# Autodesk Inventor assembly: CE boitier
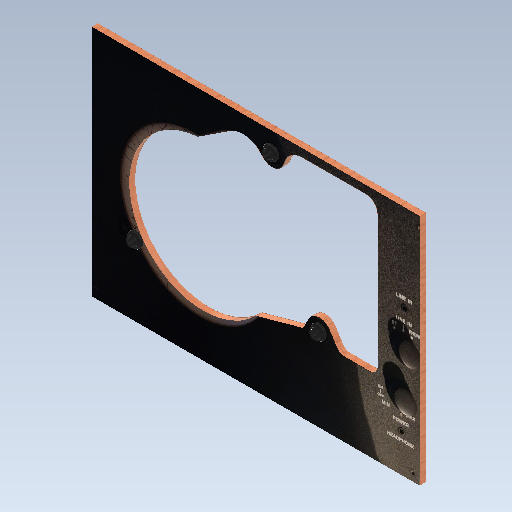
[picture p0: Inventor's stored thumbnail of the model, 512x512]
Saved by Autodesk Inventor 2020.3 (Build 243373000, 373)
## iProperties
Created: 2020-09
Part Number: CE boitier
Document SubType Name: Assembly
Designer: ficho
Author: ficho
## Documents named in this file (3)
- G:\travail\année 2020-2021\2I2D\platine disque\platine 3D\CE boitier.iam
- G:\travail\année 2020-2021\2I2D\platine disque\platine 3D\amortisseur.ipt
- G:\travail\année 2020-2021\2I2D\platine disque\platine 3D\plaque bois.ipt
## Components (4 placed, 2 different names)
1. amortisseur:1 — Logement:1
2. plaque bois:1 — Logement:1, Logement:2, Logement:3
3. amortisseur:2 — Logement:2
4. amortisseur:3 — Logement:3
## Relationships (3: Insert 3)
- Logement:1 [Insert]: amortisseur:1 ↔ plaque bois:1
- Logement:2 [Insert]: plaque bois:1 ↔ amortisseur:2
- Logement:3 [Insert]: plaque bois:1 ↔ amortisseur:3
